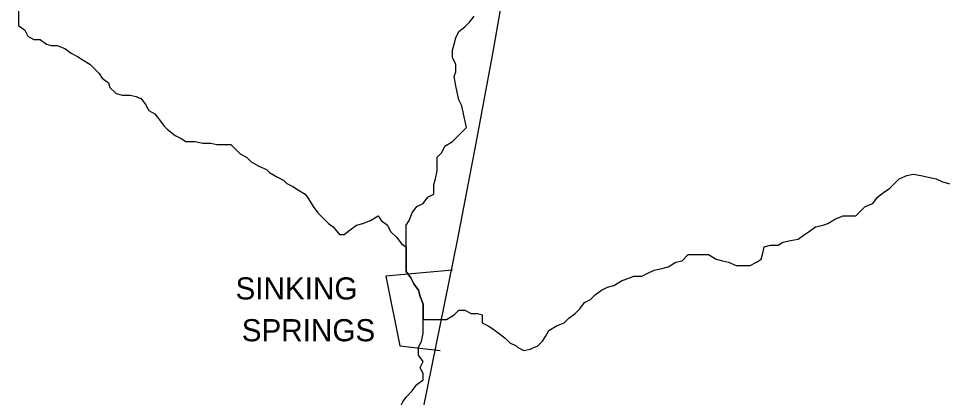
# Model space of a CAD drawing. Extents: x 0 to 34, y 0 to 22.
# Drawn here: x 4.327 to 5.139, y 17.836 to 18.17 of the extents above; entities that cross this region are included whole.
import ezdxf

# ---------------------------------------------------------------- set-up
doc = ezdxf.new("R2010")
doc.units = 0
doc.layers.add('Default', color=7, linetype='Continuous')

msp = doc.modelspace()

# ---------------------------------------------------------------- linework, layer by layer
at = {"layer": 'Default'}
for points in [[(4.80243, 18.46879), (4.77789, 18.33653), (4.75744, 18.21928), (4.74381, 18.1402), (4.72881, 18.05976), (4.71245, 17.97386), (4.68245, 17.82661)], [(4.33614, 18.267), (4.33614, 18.26018), (4.33614, 18.25337), (4.33478, 18.24791), (4.33478, 18.24109), (4.33342, 18.23428), (4.33342, 18.22746), (4.33205, 18.22064), (4.33205, 18.21519), (4.33205, 18.20837), (4.32933, 18.20292), (4.32933, 18.19474), (4.32933, 18.18928), (4.32796, 18.18247), (4.3266, 18.17565), (4.3266, 18.1702), (4.3266, 18.16338), (4.3266, 18.16338)], [(4.66745, 17.96841), (4.66745, 17.97386), (4.66745, 17.97932), (4.66745, 17.9875), (4.67018, 17.99159), (4.67291, 17.99841), (4.677, 18.00386), (4.68245, 18.00659), (4.68654, 18.01204), (4.692, 18.01477), (4.692, 18.02295), (4.69336, 18.0284), (4.69472, 18.03522), (4.69472, 18.04067), (4.69472, 18.04749), (4.69881, 18.05158), (4.70154, 18.05703), (4.70836, 18.06112), (4.71245, 18.06521), (4.71654, 18.0693), (4.72063, 18.07339), (4.71926, 18.08021), (4.7179, 18.08566), (4.71654, 18.09248), (4.71381, 18.09794), (4.71245, 18.10475), (4.71108, 18.11021), (4.70972, 18.11839), (4.71108, 18.12248), (4.71108, 18.12929), (4.70836, 18.13475), (4.70836, 18.14157), (4.70972, 18.14702), (4.71108, 18.15247), (4.71381, 18.15793), (4.71926, 18.16202), (4.72335, 18.16611), (4.72744, 18.17156)], [(4.3266, 18.16338), (4.33205, 18.15929), (4.33478, 18.15384), (4.34023, 18.15111), (4.34569, 18.15111), (4.35114, 18.14702), (4.35523, 18.14566), (4.36068, 18.14566), (4.3675, 18.14293), (4.37296, 18.13884), (4.37841, 18.13611), (4.3825, 18.13338), (4.38932, 18.12929), (4.39204, 18.12657), (4.3975, 18.12111), (4.40022, 18.11702), (4.40568, 18.11293), (4.40704, 18.10884), (4.41249, 18.10339), (4.41795, 18.10203), (4.42477, 18.10203), (4.43022, 18.10066), (4.43295, 18.0993), (4.43431, 18.0993)], [(4.43431, 18.0993), (4.4384, 18.09385), (4.44113, 18.08839), (4.44658, 18.08566), (4.45067, 18.08021), (4.45476, 18.07476), (4.45749, 18.07203), (4.4643, 18.06658), (4.46976, 18.06385), (4.47385, 18.06112), (4.48203, 18.06112), (4.48885, 18.05976), (4.49566, 18.05976), (4.50112, 18.0584), (4.50657, 18.0584), (4.51339, 18.0584), (4.51748, 18.05431), (4.52157, 18.05022), (4.52702, 18.04749), (4.53111, 18.0434), (4.53793, 18.03931), (4.54475, 18.03658), (4.54747, 18.03385), (4.55429, 18.02976), (4.55974, 18.02704), (4.56111, 18.02567), (4.56247, 18.02431)], [(5.05603, 17.99568), (5.06285, 17.99568), (5.06694, 17.99977), (5.07103, 18.00386), (5.07784, 18.00659), (5.08193, 18.01204), (5.08739, 18.01613), (5.09284, 18.02022), (5.09693, 18.02431), (5.10102, 18.0284), (5.10784, 18.03113), (5.11329, 18.03249), (5.12011, 18.03113), (5.12693, 18.02976), (5.13374, 18.0284), (5.1392, 18.02567), (5.14465, 18.02431), (5.15147, 18.02295), (5.15829, 18.02295), (5.1651, 18.02022), (5.16919, 18.01886), (5.17601, 18.01886), (5.17601, 18.01886)], [(4.56247, 18.02431), (4.56792, 18.02158), (4.57201, 18.01886), (4.57883, 18.01477), (4.58156, 18.01068), (4.58565, 18.00386), (4.58974, 17.99841), (4.59383, 17.99432), (4.59928, 17.98886), (4.60337, 17.98614), (4.60883, 17.97932), (4.61292, 17.97932), (4.61837, 17.98341), (4.62382, 17.9875), (4.62928, 17.98886), (4.6361, 17.99159), (4.64291, 17.99568), (4.64564, 17.99159), (4.65109, 17.9875), (4.65382, 17.98204), (4.65927, 17.97659), (4.66336, 17.97114), (4.66745, 17.96841), (4.66745, 17.96841)], [(4.92105, 17.96159), (4.92787, 17.96159), (4.93332, 17.96159), (4.94014, 17.9575), (4.94559, 17.95614), (4.95105, 17.95478), (4.95786, 17.95205), (4.96332, 17.95205), (4.97013, 17.95205), (4.97559, 17.95478), (4.97968, 17.9575), (4.98104, 17.96296), (4.9824, 17.96841), (4.98786, 17.96977), (4.99467, 17.96977), (4.99877, 17.9725), (5.00558, 17.97386), (5.0124, 17.97523), (5.01785, 17.97932), (5.02194, 17.98204), (5.0274, 17.98614), (5.03421, 17.9875), (5.0383, 17.98886), (5.04512, 17.99295), (5.05194, 17.99568), (5.05603, 17.99568), (5.05603, 17.99568)], [(4.66745, 17.96841), (4.66745, 17.96568), (4.66745, 17.95887), (4.66745, 17.95341), (4.66745, 17.9466), (4.67154, 17.94114), (4.67427, 17.93569), (4.67836, 17.93023), (4.67972, 17.92478), (4.68245, 17.91796), (4.68245, 17.91251), (4.68245, 17.90433)], [(4.68245, 17.90433), (4.68245, 17.91251), (4.68245, 17.91796), (4.67972, 17.92478), (4.67836, 17.93023), (4.67427, 17.93569), (4.67154, 17.94114), (4.66745, 17.9466), (4.66745, 17.95341), (4.66745, 17.95887), (4.66745, 17.96568), (4.66745, 17.96841)], [(4.76562, 17.87979), (4.77107, 17.87706), (4.77653, 17.87842), (4.78334, 17.88115), (4.78744, 17.88524), (4.79016, 17.88933), (4.79289, 17.89479), (4.79971, 17.89888), (4.80652, 17.9016), (4.81061, 17.90569), (4.81607, 17.90978), (4.82016, 17.91387), (4.82425, 17.91933), (4.8297, 17.92205), (4.83379, 17.92614), (4.83924, 17.93023), (4.8447, 17.93296), (4.85015, 17.93433), (4.85697, 17.93842), (4.86379, 17.94114), (4.86788, 17.94251), (4.87469, 17.94251), (4.88015, 17.94523), (4.8856, 17.94796), (4.89242, 17.94932), (4.89787, 17.95069), (4.90469, 17.95478), (4.91014, 17.95614), (4.9156, 17.96159), (4.91969, 17.96159), (4.92105, 17.96159), (4.92105, 17.96159)], [(4.70836, 17.94796), (4.64973, 17.94251), (4.662, 17.88115), (4.69745, 17.87706)], [(4.69881, 17.90433), (4.7029, 17.90433), (4.70972, 17.90842), (4.71381, 17.91251), (4.71926, 17.91251), (4.72472, 17.90978), (4.73017, 17.90978), (4.73426, 17.90842), (4.73426, 17.9016), (4.73972, 17.89888), (4.74381, 17.89615), (4.74926, 17.89206), (4.75471, 17.88797), (4.7588, 17.88388), (4.76426, 17.88115), (4.76426, 17.88115), (4.76562, 17.87979)], [(4.662, 17.82116), (4.662, 17.82661), (4.66473, 17.83207), (4.66745, 17.83616), (4.67291, 17.84161), (4.677, 17.84707), (4.68245, 17.85116), (4.68245, 17.85661), (4.67972, 17.86206), (4.68245, 17.86752), (4.67836, 17.87297), (4.67836, 17.87979), (4.68109, 17.88524), (4.68245, 17.89206), (4.68245, 17.90024), (4.68245, 17.90433), (4.68245, 17.90433)], [(4.68245, 17.90433), (4.68791, 17.90433), (4.69472, 17.90433), (4.69881, 17.90433)]]:
    msp.add_lwpolyline(points, dxfattribs=at)

# ---------------------------------------------------------------- texts
for s, p in [('SINKING', (4.51748, 17.92205)), ('SPRINGS', (4.52293, 17.88524))]:
    msp.add_text(s, height=0.019502, dxfattribs=at).set_placement(p)

doc.saveas('drawing.dxf')
